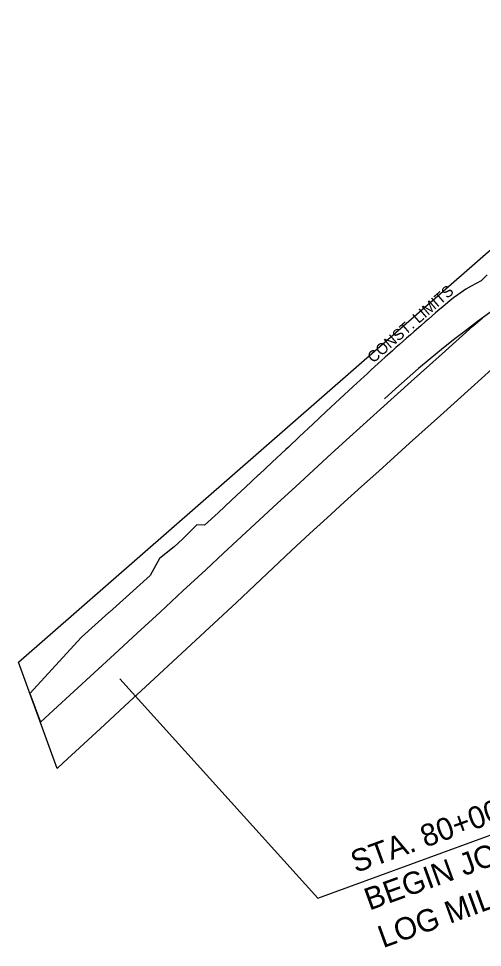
# Model space of a CAD drawing. Extents: x 1710782 to 1712392, y 548480 to 549912.
# Drawn here: x 1710782 to 1711033, y 548762 to 549264 of the extents above; entities that cross this region are included whole.
import ezdxf

# ---------------------------------------------------------------- set-up
doc = ezdxf.new("R2010")
doc.units = 0
for name, color, linetype in [('R_Erosion_STG 2', 7, 'Continuous'), ('R_Horz Alg Annot', 7, 'Continuous'), ('R_MOT', 7, 'Continuous')]:
    doc.layers.add(name, color=color, linetype=linetype)

msp = doc.modelspace()

# ---------------------------------------------------------------- linework, layer by layer
at = {"layer": 'R_Erosion_STG 2'}
msp.add_arc((1711398.54, 548605.45), 617.11, 108.54528, 132.74131, dxfattribs=at)
at = {"layer": 'R_Horz Alg Annot'}
msp.add_line((1710943.56, 548788.87), (1711117.78, 548852.28), dxfattribs=at)
msp.add_lwpolyline([(1710943.56, 548788.87), (1710836.53, 548907.29)], dxfattribs=at)
at = {"layer": 'R_MOT'}
msp.add_line((1710781.74, 548916.29), (1711226.5, 549304.64), dxfattribs=at)
for points in [[(1711035.11, 549125.61), (1711031.93, 549122.45)], [(1711035.11, 549125.61), (1711031.93, 549122.45)], [(1711035.11, 549125.61), (1711031.93, 549122.45)], [(1711035.11, 549125.61), (1711031.93, 549122.45)], [(1711035.11, 549125.61), (1711031.93, 549122.45)], [(1711035.11, 549125.61), (1711031.93, 549122.45)], [(1711035.11, 549125.61), (1711031.93, 549122.45)], [(1711035.11, 549125.61), (1711031.93, 549122.45)], [(1711031.93, 549122.45), (1711026.57, 549119.45), (1711023.65, 549117.81), (1711019.35, 549114.91), (1711018.08, 549113.95), (1711017.75, 549113.69), (1711015.26, 549111.72), (1711011.27, 549108.4), (1711009.61, 549107), (1711007.31, 549105.06), (1711003.37, 549101.69), (1711001.61, 549100.16), (1710999.45, 549098.3), (1710995.53, 549094.91), (1710993.66, 549093.28), (1710991.63, 549091.5), (1710987.76, 549088.07), (1710985.79, 549086.31), (1710983.9, 549084.62), (1710980.05, 549081.16), (1710977.97, 549079.29), (1710976.21, 549077.7), (1710972.4, 549074.21), (1710970.21, 549072.2), (1710968.59, 549070.7), (1710962.8, 549065.34), (1710955.45, 549058.55), (1710948.12, 549051.75), (1710940.82, 549044.92), (1710933.51, 549038.09), (1710927.67, 549032.6), (1710926.21, 549031.25), (1710918.91, 549024.42), (1710911.79, 549017.8), (1710911.59, 549017.61), (1710907.95, 549014.19), (1710904.29, 549010.77), (1710902.1, 549008.73), (1710896.99, 549003.94), (1710889.69, 548997.11), (1710882.38, 548990.28)], [(1711031.93, 549122.45), (1711026.57, 549119.45), (1711023.65, 549117.81), (1711019.35, 549114.91), (1711018.08, 549113.95), (1711017.75, 549113.69), (1711015.26, 549111.72), (1711011.27, 549108.4), (1711009.61, 549107), (1711007.31, 549105.06), (1711003.37, 549101.69), (1711001.61, 549100.16), (1710999.45, 549098.3), (1710995.53, 549094.91), (1710993.66, 549093.28), (1710991.63, 549091.5), (1710987.76, 549088.07), (1710985.79, 549086.31), (1710983.9, 549084.62), (1710980.05, 549081.16), (1710977.97, 549079.29), (1710976.21, 549077.7), (1710972.4, 549074.21), (1710970.21, 549072.2), (1710968.59, 549070.7), (1710962.8, 549065.34), (1710955.45, 549058.55), (1710948.12, 549051.75), (1710940.82, 549044.92), (1710933.51, 549038.09), (1710927.67, 549032.6), (1710926.21, 549031.25), (1710918.91, 549024.42), (1710911.79, 549017.8), (1710911.59, 549017.61), (1710907.95, 549014.19), (1710904.29, 549010.77), (1710902.1, 549008.73), (1710896.99, 549003.94), (1710889.69, 548997.11), (1710882.38, 548990.28)], [(1711031.93, 549122.45), (1711026.57, 549119.45), (1711023.65, 549117.81), (1711019.35, 549114.91), (1711018.08, 549113.95), (1711017.75, 549113.69), (1711015.26, 549111.72), (1711011.27, 549108.4), (1711009.61, 549107), (1711007.31, 549105.06), (1711003.37, 549101.69), (1711001.61, 549100.16), (1710999.45, 549098.3), (1710995.53, 549094.91), (1710993.66, 549093.28), (1710991.63, 549091.5), (1710987.76, 549088.07), (1710985.79, 549086.31), (1710983.9, 549084.62), (1710980.05, 549081.16), (1710977.97, 549079.29), (1710976.21, 549077.7), (1710972.4, 549074.21), (1710970.21, 549072.2), (1710968.59, 549070.7), (1710962.8, 549065.34), (1710955.45, 549058.55), (1710948.12, 549051.75), (1710940.82, 549044.92), (1710933.51, 549038.09), (1710927.67, 549032.6), (1710926.21, 549031.25), (1710918.91, 549024.42), (1710911.79, 549017.8), (1710911.59, 549017.61), (1710907.95, 549014.19), (1710904.29, 549010.77), (1710902.1, 549008.73), (1710896.99, 549003.94), (1710889.69, 548997.11), (1710882.38, 548990.28)], [(1711031.93, 549122.45), (1711026.57, 549119.45), (1711023.65, 549117.81), (1711019.35, 549114.91), (1711018.08, 549113.95), (1711017.75, 549113.69), (1711015.26, 549111.72), (1711011.27, 549108.4), (1711009.61, 549107), (1711007.31, 549105.06), (1711003.37, 549101.69), (1711001.61, 549100.16), (1710999.45, 549098.3), (1710995.53, 549094.91), (1710993.66, 549093.28), (1710991.63, 549091.5), (1710987.76, 549088.07), (1710985.79, 549086.31), (1710983.9, 549084.62), (1710980.05, 549081.16), (1710977.97, 549079.29), (1710976.21, 549077.7), (1710972.4, 549074.21), (1710970.21, 549072.2), (1710968.59, 549070.7), (1710962.8, 549065.34), (1710955.45, 549058.55), (1710948.12, 549051.75), (1710940.82, 549044.92), (1710933.51, 549038.09), (1710927.67, 549032.6), (1710926.21, 549031.25), (1710918.91, 549024.42), (1710911.79, 549017.8), (1710911.59, 549017.61), (1710907.95, 549014.19), (1710904.29, 549010.77), (1710902.1, 549008.73), (1710896.99, 549003.94), (1710889.69, 548997.11), (1710882.38, 548990.28)], [(1711031.93, 549122.45), (1711026.57, 549119.45), (1711023.65, 549117.81), (1711019.35, 549114.91), (1711018.08, 549113.95), (1711017.75, 549113.69), (1711015.26, 549111.72), (1711011.27, 549108.4), (1711009.61, 549107), (1711007.31, 549105.06), (1711003.37, 549101.69), (1711001.61, 549100.16), (1710999.45, 549098.3), (1710995.53, 549094.91), (1710993.66, 549093.28), (1710991.63, 549091.5), (1710987.76, 549088.07), (1710985.79, 549086.31), (1710983.9, 549084.62), (1710980.05, 549081.16), (1710977.97, 549079.29), (1710976.21, 549077.7), (1710972.4, 549074.21), (1710970.21, 549072.2), (1710968.59, 549070.7), (1710962.8, 549065.34), (1710955.45, 549058.55), (1710948.12, 549051.75), (1710940.82, 549044.92), (1710933.51, 549038.09), (1710927.67, 549032.6), (1710926.21, 549031.25), (1710918.91, 549024.42), (1710911.79, 549017.8), (1710911.59, 549017.61), (1710907.95, 549014.19), (1710904.29, 549010.77), (1710902.1, 549008.73), (1710896.99, 549003.94), (1710889.69, 548997.11), (1710882.38, 548990.28)], [(1711031.93, 549122.45), (1711026.57, 549119.45), (1711023.65, 549117.81), (1711019.35, 549114.91), (1711018.08, 549113.95), (1711017.75, 549113.69), (1711015.26, 549111.72), (1711011.27, 549108.4), (1711009.61, 549107), (1711007.31, 549105.06), (1711003.37, 549101.69), (1711001.61, 549100.16), (1710999.45, 549098.3), (1710995.53, 549094.91), (1710993.66, 549093.28), (1710991.63, 549091.5), (1710987.76, 549088.07), (1710985.79, 549086.31), (1710983.9, 549084.62), (1710980.05, 549081.16), (1710977.97, 549079.29), (1710976.21, 549077.7), (1710972.4, 549074.21), (1710970.21, 549072.2), (1710968.59, 549070.7), (1710962.8, 549065.34), (1710955.45, 549058.55), (1710948.12, 549051.75), (1710940.82, 549044.92), (1710933.51, 549038.09), (1710927.67, 549032.6), (1710926.21, 549031.25), (1710918.91, 549024.42), (1710911.79, 549017.8), (1710911.59, 549017.61), (1710907.95, 549014.19), (1710904.29, 549010.77), (1710902.1, 549008.73), (1710896.99, 549003.94), (1710889.69, 548997.11), (1710882.38, 548990.28)], [(1711031.93, 549122.45), (1711026.57, 549119.45), (1711023.65, 549117.81), (1711019.35, 549114.91), (1711018.08, 549113.95), (1711017.75, 549113.69), (1711015.26, 549111.72), (1711011.27, 549108.4), (1711009.61, 549107), (1711007.31, 549105.06), (1711003.37, 549101.69), (1711001.61, 549100.16), (1710999.45, 549098.3), (1710995.53, 549094.91), (1710993.66, 549093.28), (1710991.63, 549091.5), (1710987.76, 549088.07), (1710985.79, 549086.31), (1710983.9, 549084.62), (1710980.05, 549081.16), (1710977.97, 549079.29), (1710976.21, 549077.7), (1710972.4, 549074.21), (1710970.21, 549072.2), (1710968.59, 549070.7), (1710962.8, 549065.34), (1710955.45, 549058.55), (1710948.12, 549051.75), (1710940.82, 549044.92), (1710933.51, 549038.09), (1710927.67, 549032.6), (1710926.21, 549031.25), (1710918.91, 549024.42), (1710911.79, 549017.8), (1710911.59, 549017.61), (1710907.95, 549014.19), (1710904.29, 549010.77), (1710902.1, 549008.73), (1710896.99, 549003.94), (1710889.69, 548997.11), (1710882.38, 548990.28)], [(1711031.93, 549122.45), (1711026.57, 549119.45), (1711023.65, 549117.81), (1711019.35, 549114.91), (1711018.08, 549113.95), (1711017.75, 549113.69), (1711015.26, 549111.72), (1711011.27, 549108.4), (1711009.61, 549107), (1711007.31, 549105.06), (1711003.37, 549101.69), (1711001.61, 549100.16), (1710999.45, 549098.3), (1710995.53, 549094.91), (1710993.66, 549093.28), (1710991.63, 549091.5), (1710987.76, 549088.07), (1710985.79, 549086.31), (1710983.9, 549084.62), (1710980.05, 549081.16), (1710977.97, 549079.29), (1710976.21, 549077.7), (1710972.4, 549074.21), (1710970.21, 549072.2), (1710968.59, 549070.7), (1710962.8, 549065.34), (1710955.45, 549058.55), (1710948.12, 549051.75), (1710940.82, 549044.92), (1710933.51, 549038.09), (1710927.67, 549032.6), (1710926.21, 549031.25), (1710918.91, 549024.42), (1710911.79, 549017.8), (1710911.59, 549017.61), (1710907.95, 549014.19), (1710904.29, 549010.77), (1710902.1, 549008.73), (1710896.99, 549003.94), (1710889.69, 548997.11), (1710882.38, 548990.28)], [(1710793.54, 548883.89), (1710800.65, 548890.43), (1710811.64, 548900.53), (1710822.62, 548910.62), (1710833.61, 548920.71), (1710845.94, 548932.07), (1710858.28, 548943.43), (1710870.62, 548954.79), (1710882.95, 548966.15), (1710892.67, 548975.17), (1710902.38, 548984.19), (1710912.1, 548993.2), (1710921.81, 549002.22), (1710931.54, 549011.16), (1710941.27, 549020.11), (1710951, 549029.06), (1710960.74, 549038), (1710977.43, 549053), (1710994.12, 549067.99), (1711010.82, 549082.98), (1711027.51, 549097.98), (1711032.63, 549102.38)], [(1710793.54, 548883.89), (1710800.65, 548890.43), (1710811.64, 548900.53), (1710822.62, 548910.62), (1710833.61, 548920.71), (1710845.94, 548932.07), (1710858.28, 548943.43), (1710870.62, 548954.79), (1710882.95, 548966.15), (1710892.67, 548975.17), (1710902.38, 548984.19), (1710912.1, 548993.2), (1710921.81, 549002.22), (1710931.54, 549011.16), (1710941.27, 549020.11), (1710951, 549029.06), (1710960.74, 549038), (1710977.43, 549053), (1710994.12, 549067.99), (1711010.82, 549082.98), (1711027.51, 549097.98), (1711032.63, 549102.38)], [(1710793.54, 548883.89), (1710800.65, 548890.43), (1710811.64, 548900.53), (1710822.62, 548910.62), (1710833.61, 548920.71), (1710845.94, 548932.07), (1710858.28, 548943.43), (1710870.62, 548954.79), (1710882.95, 548966.15), (1710892.67, 548975.17), (1710902.38, 548984.19), (1710912.1, 548993.2), (1710921.81, 549002.22), (1710931.54, 549011.16), (1710941.27, 549020.11), (1710951, 549029.06), (1710960.74, 549038), (1710977.43, 549053), (1710994.12, 549067.99), (1711010.82, 549082.98), (1711027.51, 549097.98), (1711032.63, 549102.38)], [(1710793.54, 548883.89), (1710800.65, 548890.43), (1710811.64, 548900.53), (1710822.62, 548910.62), (1710833.61, 548920.71), (1710845.94, 548932.07), (1710858.28, 548943.43), (1710870.62, 548954.79), (1710882.95, 548966.15), (1710892.67, 548975.17), (1710902.38, 548984.19), (1710912.1, 548993.2), (1710921.81, 549002.22), (1710931.54, 549011.16), (1710941.27, 549020.11), (1710951, 549029.06), (1710960.74, 549038), (1710977.43, 549053), (1710994.12, 549067.99), (1711010.82, 549082.98), (1711027.51, 549097.98), (1711032.63, 549102.38)], [(1710793.54, 548883.89), (1710800.65, 548890.43), (1710811.64, 548900.53), (1710822.62, 548910.62), (1710833.61, 548920.71), (1710845.94, 548932.07), (1710858.28, 548943.43), (1710870.62, 548954.79), (1710882.95, 548966.15), (1710892.67, 548975.17), (1710902.38, 548984.19), (1710912.1, 548993.2), (1710921.81, 549002.22), (1710931.54, 549011.16), (1710941.27, 549020.11), (1710951, 549029.06), (1710960.74, 549038), (1710977.43, 549053), (1710994.12, 549067.99), (1711010.82, 549082.98), (1711027.51, 549097.98), (1711032.63, 549102.38)], [(1710793.54, 548883.89), (1710800.65, 548890.43), (1710811.64, 548900.53), (1710822.62, 548910.62), (1710833.61, 548920.71), (1710845.94, 548932.07), (1710858.28, 548943.43), (1710870.62, 548954.79), (1710882.95, 548966.15), (1710892.67, 548975.17), (1710902.38, 548984.19), (1710912.1, 548993.2), (1710921.81, 549002.22), (1710931.54, 549011.16), (1710941.27, 549020.11), (1710951, 549029.06), (1710960.74, 549038), (1710977.43, 549053), (1710994.12, 549067.99), (1711010.82, 549082.98), (1711027.51, 549097.98), (1711032.63, 549102.38)], [(1710793.54, 548883.89), (1710800.65, 548890.43), (1710811.64, 548900.53), (1710822.62, 548910.62), (1710833.61, 548920.71), (1710845.94, 548932.07), (1710858.28, 548943.43), (1710870.62, 548954.79), (1710882.95, 548966.15), (1710892.67, 548975.17), (1710902.38, 548984.19), (1710912.1, 548993.2), (1710921.81, 549002.22), (1710931.54, 549011.16), (1710941.27, 549020.11), (1710951, 549029.06), (1710960.74, 549038), (1710977.43, 549053), (1710994.12, 549067.99), (1711010.82, 549082.98), (1711027.51, 549097.98), (1711032.63, 549102.38)], [(1710793.54, 548883.89), (1710800.65, 548890.43), (1710811.64, 548900.53), (1710822.62, 548910.62), (1710833.61, 548920.71), (1710845.94, 548932.07), (1710858.28, 548943.43), (1710870.62, 548954.79), (1710882.95, 548966.15), (1710892.67, 548975.17), (1710902.38, 548984.19), (1710912.1, 548993.2), (1710921.81, 549002.22), (1710931.54, 549011.16), (1710941.27, 549020.11), (1710951, 549029.06), (1710960.74, 549038), (1710977.43, 549053), (1710994.12, 549067.99), (1711010.82, 549082.98), (1711027.51, 549097.98), (1711032.63, 549102.38)], [(1711043.26, 549079.63), (1711026.58, 549064.63), (1711009.91, 549049.63), (1710993.23, 549034.63), (1710976.56, 549019.63), (1710967.24, 549011.2), (1710957.92, 549002.77), (1710948.6, 548994.34), (1710939.28, 548985.91), (1710929.38, 548976.59), (1710919.47, 548967.26), (1710909.57, 548957.93), (1710899.67, 548948.6), (1710887.35, 548937.19), (1710875.03, 548925.79), (1710862.71, 548914.38), (1710850.39, 548902.97), (1710839.28, 548892.73), (1710828.17, 548882.48), (1710817.05, 548872.24), (1710805.94, 548862), (1710802.62, 548858.94)], [(1710882.38, 548990.28), (1710878.09, 548990.5), (1710873.14, 548985.54), (1710872.44, 548984.83), (1710870.35, 548982.74), (1710865.95, 548978.59), (1710858.03, 548972.43), (1710852.9, 548963.24)], [(1710882.38, 548990.28), (1710878.09, 548990.5), (1710873.14, 548985.54), (1710872.44, 548984.83), (1710870.35, 548982.74), (1710865.95, 548978.59), (1710858.03, 548972.43), (1710852.9, 548963.24)], [(1710882.38, 548990.28), (1710878.09, 548990.5), (1710873.14, 548985.54), (1710872.44, 548984.83), (1710870.35, 548982.74), (1710865.95, 548978.59), (1710858.03, 548972.43), (1710852.9, 548963.24)], [(1710882.38, 548990.28), (1710878.09, 548990.5), (1710873.14, 548985.54), (1710872.44, 548984.83), (1710870.35, 548982.74), (1710865.95, 548978.59), (1710858.03, 548972.43), (1710852.9, 548963.24)], [(1710882.38, 548990.28), (1710878.09, 548990.5), (1710873.14, 548985.54), (1710872.44, 548984.83), (1710870.35, 548982.74), (1710865.95, 548978.59), (1710858.03, 548972.43), (1710852.9, 548963.24)], [(1710882.38, 548990.28), (1710878.09, 548990.5), (1710873.14, 548985.54), (1710872.44, 548984.83), (1710870.35, 548982.74), (1710865.95, 548978.59), (1710858.03, 548972.43), (1710852.9, 548963.24)], [(1710882.38, 548990.28), (1710878.09, 548990.5), (1710873.14, 548985.54), (1710872.44, 548984.83), (1710870.35, 548982.74), (1710865.95, 548978.59), (1710858.03, 548972.43), (1710852.9, 548963.24)], [(1710882.38, 548990.28), (1710878.09, 548990.5), (1710873.14, 548985.54), (1710872.44, 548984.83), (1710870.35, 548982.74), (1710865.95, 548978.59), (1710858.03, 548972.43), (1710852.9, 548963.24)], [(1710852.9, 548963.24), (1710845.47, 548956.55), (1710838.05, 548949.85), (1710830.91, 548943.43), (1710830.61, 548943.16), (1710823.15, 548936.5), (1710815.76, 548929.77), (1710815.76, 548929.77)], [(1710852.9, 548963.24), (1710845.47, 548956.55), (1710838.05, 548949.85), (1710830.91, 548943.43), (1710830.61, 548943.16), (1710823.15, 548936.5), (1710815.76, 548929.77), (1710815.76, 548929.77)], [(1710852.9, 548963.24), (1710845.47, 548956.55), (1710838.05, 548949.85), (1710830.91, 548943.43), (1710830.61, 548943.16), (1710823.15, 548936.5), (1710815.76, 548929.77), (1710815.76, 548929.77)], [(1710852.9, 548963.24), (1710845.47, 548956.55), (1710838.05, 548949.85), (1710830.91, 548943.43), (1710830.61, 548943.16), (1710823.15, 548936.5), (1710815.76, 548929.77), (1710815.76, 548929.77)], [(1710852.9, 548963.24), (1710845.47, 548956.55), (1710838.05, 548949.85), (1710830.91, 548943.43), (1710830.61, 548943.16), (1710823.15, 548936.5), (1710815.76, 548929.77), (1710815.76, 548929.77)], [(1710852.9, 548963.24), (1710845.47, 548956.55), (1710838.05, 548949.85), (1710830.91, 548943.43), (1710830.61, 548943.16), (1710823.15, 548936.5), (1710815.76, 548929.77), (1710815.76, 548929.77)], [(1710852.9, 548963.24), (1710845.47, 548956.55), (1710838.05, 548949.85), (1710830.91, 548943.43), (1710830.61, 548943.16), (1710823.15, 548936.5), (1710815.76, 548929.77), (1710815.76, 548929.77)], [(1710852.9, 548963.24), (1710845.47, 548956.55), (1710838.05, 548949.85), (1710830.91, 548943.43), (1710830.61, 548943.16), (1710823.15, 548936.5), (1710815.76, 548929.77), (1710815.76, 548929.77)], [(1710815.76, 548929.77), (1710787.88, 548899.43)], [(1710815.76, 548929.77), (1710787.88, 548899.43)], [(1710815.76, 548929.77), (1710787.88, 548899.43)], [(1710815.76, 548929.77), (1710787.88, 548899.43)], [(1710815.76, 548929.77), (1710787.88, 548899.43)], [(1710815.76, 548929.77), (1710787.88, 548899.43)], [(1710815.76, 548929.77), (1710787.88, 548899.43)], [(1710815.76, 548929.77), (1710787.88, 548899.43)], [(1710802.62, 548858.94), (1710781.74, 548916.29)], [(1710787.88, 548899.43), (1710793.54, 548883.89)], [(1710787.88, 548899.43), (1710793.54, 548883.89)], [(1710787.88, 548899.43), (1710793.54, 548883.89)], [(1710787.88, 548899.43), (1710793.54, 548883.89)], [(1710787.88, 548899.43), (1710793.54, 548883.89)], [(1710787.88, 548899.43), (1710793.54, 548883.89)], [(1710787.88, 548899.43), (1710793.54, 548883.89)]]:
    msp.add_lwpolyline(points, dxfattribs=at)

# ---------------------------------------------------------------- texts
at = {"layer": 'R_Horz Alg Annot'}
for s, height, rotation, p in [('CONST. LIMITS', 6, 41.1002, (1710973.61, 549077.66)), ('STA. 80+00.00', 12, 20, (1710964.1, 548802.33)), ('BEGIN JOB 100942', 12, 20, (1710971.48, 548782.04)), ('LOG MILE 0.44', 12, 20, (1710978.87, 548761.74))]:
    msp.add_text(s, height=height, rotation=rotation, dxfattribs=at).set_placement(p)

doc.saveas('drawing.dxf')
